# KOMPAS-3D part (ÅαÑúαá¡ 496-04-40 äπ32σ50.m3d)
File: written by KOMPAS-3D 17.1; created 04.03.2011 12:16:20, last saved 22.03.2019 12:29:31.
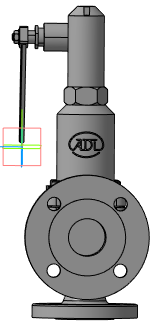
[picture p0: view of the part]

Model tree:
1. Плоскость XY
2. Плоскость ZX
3. Плоскость ZY
4. Ось X
5. Ось Y
6. Ось Z
7. Начало координат
8. Операция без истории:2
